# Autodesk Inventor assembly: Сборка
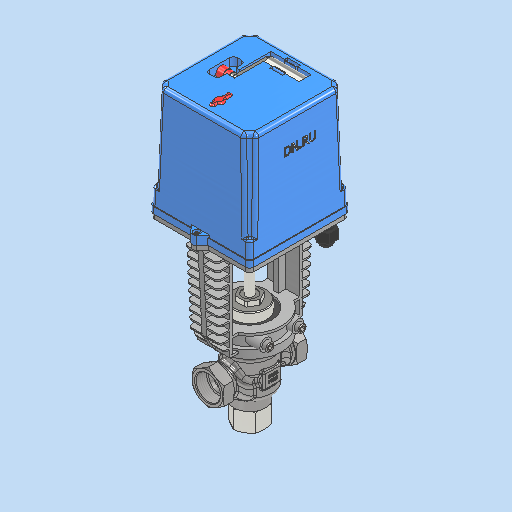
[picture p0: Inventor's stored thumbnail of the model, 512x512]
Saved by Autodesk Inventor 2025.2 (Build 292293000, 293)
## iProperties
Created: 2026-04
Part Number: Сборка
Document SubType Name: Assembly
Designer: igorr
Author: igorr
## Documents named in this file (7)
- D:\PROJECT CAD\DN.RU\...197(ACTUALE). VRg3M-S-31M-PED-T Клапан регулирующий трехходовой DN.ru\Исходники\DN25\Сборка.iam
- D:\PROJECT CAD\DN.RU\...197(ACTUALE). VRg3M-S-31M-PED-T Клапан регулирующий трехходовой DN.ru\Исходники\DN25\Деталь 1.ipt
- D:\PROJECT CAD\DN.RU\...197(ACTUALE). VRg3M-S-31M-PED-T Клапан регулирующий трехходовой DN.ru\Исходники\DN25\Деталь 2.ipt
- D:\PROJECT CAD\DN.RU\...197(ACTUALE). VRg3M-S-31M-PED-T Клапан регулирующий трехходовой DN.ru\Исходники\DN25\Деталь 3.ipt
- C:\Users\igorr\OneDrive\Документы\Inventor\Content Center Files\R2025\ru-RU\AS 1421(2)\AS 1421 - M10 x 12 засверленный конец.ipt
- C:\Users\igorr\OneDrive\Документы\Inventor\Content Center Files\R2025\ru-RU\AS 1420\AS 1420 - 1973 - M5 x 10.ipt
- C:\Users\igorr\OneDrive\Документы\Inventor\Content Center Files\R2025\ru-RU\AS 1427(05)\AS 1427 - M3 x 8(5) II.ipt
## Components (9 placed, 6 different names)
1. Деталь 1:1 — Касательность:1, Касательность:2, Угол:1, Совмещение:1, Совмещение:5, Угол:3, Совмещение:8, Совмещение:10, Совмещение:11
2. Деталь 2:1 — Касательность:1, Касательность:2, Угол:1, Совмещение:1
3. Деталь 3:1 — Совмещение:2, Совмещение:3, Угол:2, Совмещение:5, Угол:3, Совмещение:11
4. AS 1420 - метрическая M5 x 10:1 — Совмещение:8
5. AS 1420 - метрическая M5 x 10:2 — Совмещение:10
6. AS 1427 H - метрическая M3 x 8:1
7. AS 1427 H - метрическая M3 x 8:2
8. AS 1421 засверленный конец - метрическая M10 x 12 засверленный конец:1 — Заподлицо:1
9. AS 1421 засверленный конец - метрическая M10 x 12 засверленный конец:2 — Заподлицо:1
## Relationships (13: Mate 7, Angle 3, Tangent 2, Flush 1)
- Касательность:1 [Tangent]: Деталь 1:1 ↔ Деталь 2:1
- Касательность:2 [Tangent]: Деталь 1:1 ↔ Деталь 2:1
- Угол:1 [Angle]: Деталь 1:1 ↔ Деталь 2:1
- Совмещение:1 [Mate]: Деталь 1:1 ↔ Деталь 2:1
- Совмещение:2 [Mate]: Деталь 3:1
- Совмещение:3 [Mate]: Деталь 3:1
- Угол:2 [Angle]: Деталь 3:1
- Совмещение:5 [Mate]: Деталь 1:1 ↔ Деталь 3:1
- Угол:3 [Angle]: Деталь 1:1 ↔ Деталь 3:1
- Совмещение:8 [Mate]: Деталь 1:1 ↔ AS 1420 - метрическая M5 x 10:1
- Совмещение:10 [Mate]: Деталь 1:1 ↔ AS 1420 - метрическая M5 x 10:2
- Совмещение:11 [Mate]: Деталь 1:1 ↔ Деталь 3:1
- Заподлицо:1 [Flush]: AS 1421 засверленный конец - метрическая M10 x 12 засверленный конец:1 ↔ AS 1421 засверленный конец - метрическая M10 x 12 засверленный конец:2
